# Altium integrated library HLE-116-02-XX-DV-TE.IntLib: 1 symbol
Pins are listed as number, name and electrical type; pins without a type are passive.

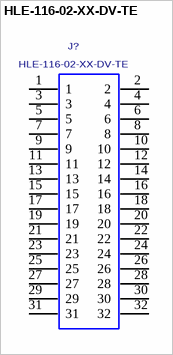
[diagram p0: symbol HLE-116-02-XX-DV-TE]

## HLE-116-02-XX-DV-TE
designator J?
.100 C.L. SINGLE BEAM SOCKET STRIP, TOP ENTRY.; MANUFACTURER: SAMTEC
footprint HLE-116-02-XX-DV-TE
pins: 1, 2, 3, 4, 5, 6, 7, 8, 9, 10, 11, 12, 13, 14, 15, 16, 17, 18, 19, 20, 21, 22, 23, 24, 25, 26, 27, 28, 29, 30, 31, 32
